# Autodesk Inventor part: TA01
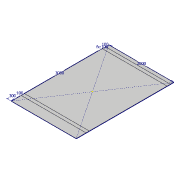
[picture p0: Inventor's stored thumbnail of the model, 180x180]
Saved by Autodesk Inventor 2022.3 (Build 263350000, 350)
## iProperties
Created: 2023-09
Part Number: TA01
Material: Generico
Document SubType Name: Modeling
Designer: Michela.Gerbotto
Density: 1 g/cm^3
Appearance: Default
Author: Michela.Gerbotto
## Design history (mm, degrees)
sketch "Schizzo1"
  geometry: L1 (-1000, 1500)-(1000, 1500); L2 (1000, 1500)-(1000, -1500); L3 (1000, -1500)-(-1000, -1500); L4 (-1000, -1500)-(-1000, 1500); L5 (-1000, 1500)-(1000, -1500); L6 (1000, 1500)-(-1000, -1500); L7 (-1000, 1200)-(1000, 1200); L8 (1000, 1200)-(1000, 1100); L9 (1000, 1100)-(-1000, 1100); L10 (-1000, 1100)-(-1000, 1200); L11 (1000, -1300)-(1000, -1400); L12 (1000, -1400)-(-1000, -1400); L13 (-1000, -1400)-(-1000, -1300); L14 (-1000, -1300)-(1000, -1300); 5 further points
  constraints: 28 end point, 6 parallel, 5 point on line, 4 perpendicular, 2 midpoint, 1 horizontal
  dimensions: "d0" = 2000 distance of L2.end L3.end; "d1" = 3000 distance of L1.end L2.end; "d2" = 100 distance of L7.end L8.end; "d3" = 100 distance between parallel lines of L12 L14 (= d2); "d4" = 100 distance between parallel lines of L3 L12; "d5" = 300 distance between parallel lines of L7 L1
extrude "Estrusione1" new body sketch "Schizzo1" distance "d6" = 5; taper "d7" = 0 deg
extrude "Estrusione2" new body sketch "Schizzo1" distance "d8" = 5; taper "d9" = 0 deg
fillet "Raccordo1" dims "d10" = 2
fillet "Raccordo2" dims "d11" = 2
node "Solido1"
node "Solido2"
